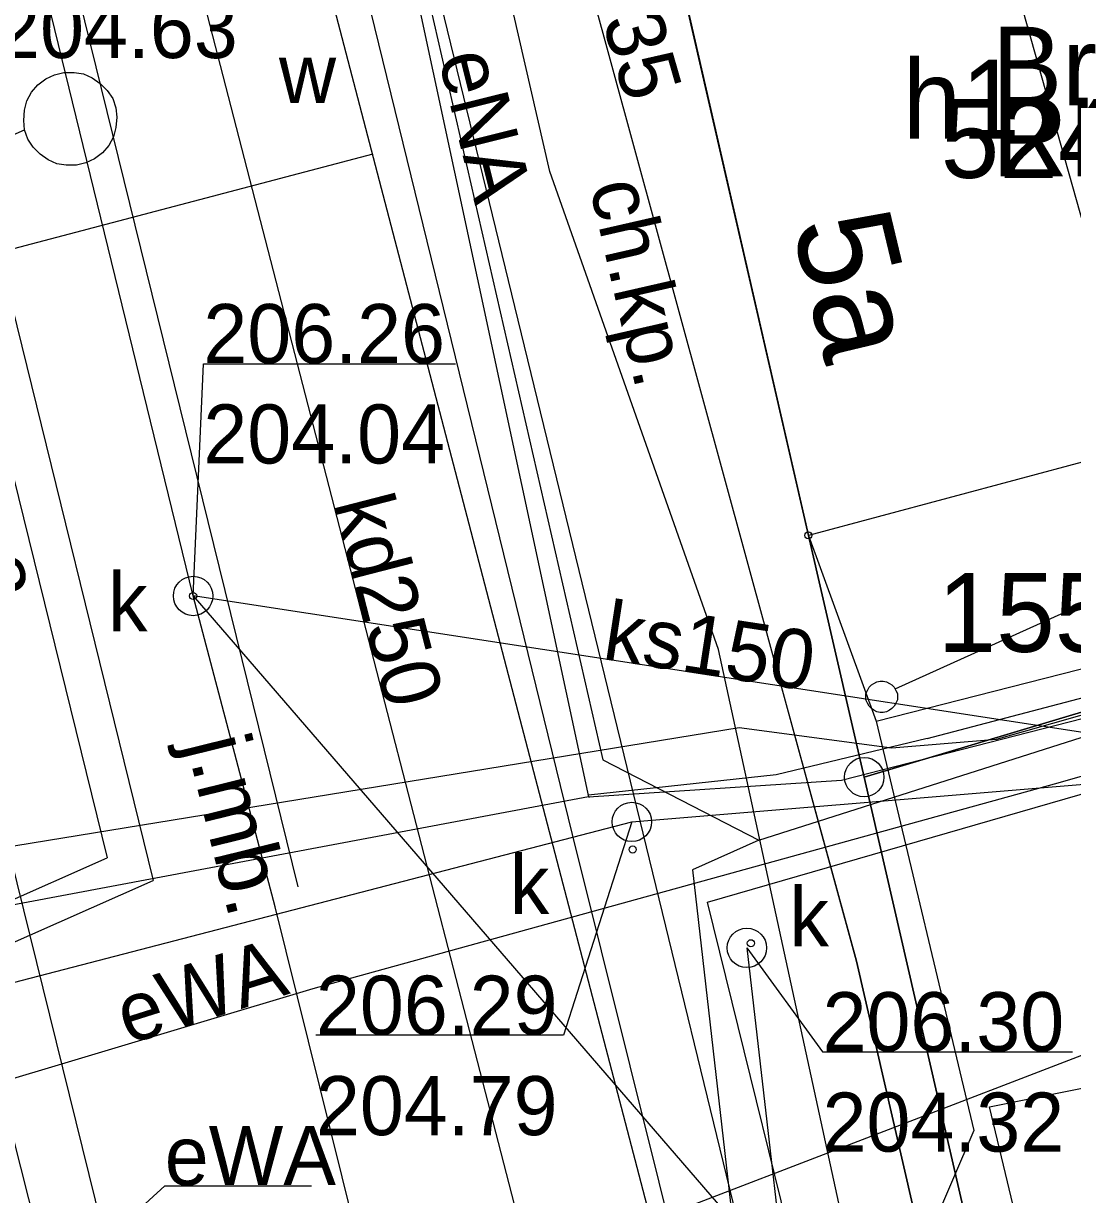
# Model space of a CAD drawing. Extents: x 6512606 to 6513006, y 6022524 to 6022728.
# Drawn here: x 6512859.01 to 6512872.32, y 6022578.56 to 6022593.43 of the extents above; entities that cross this region are included whole.
import ezdxf

# ---------------------------------------------------------------- set-up
doc = ezdxf.new("R2010")
doc.units = 0
for name, color, linetype in [('202-punkt graniczny', 7, 'Continuous'), ('203-punkt graniczny', 7, 'Continuous'), ('209-oznaczenie konturu klasyfikacyjnego', 7, 'Continuous'), ('210-oznaczenie konturu użytku gruntowego', 7, 'Continuous'), ('211-numer działki ewidencyjnej', 7, 'Continuous'), ('217-kontur klasyfikacyjny', 7, 'Continuous'), ('218-kontur użytku gruntowego', 7, 'Continuous'), ('219-działka ewidencyjna', 7, 'Continuous'), ('238-Punkt adresowy budynku', 7, 'Continuous'), ('312-budynek ewidencyjny', 7, 'Continuous'), ('312-oznaczenie budynku ewidencyjnego', 7, 'Continuous'), ('312-oznaczenie budynku ewidencyjnego-Atr117', 7, 'Continuous'), ('4', 7, 'Continuous'), ('996-Tekst dodatkowy mały', 7, 'Continuous'), ('chodnik (powierzchnia)', 7, 'Continuous'), ('chodnik (powierzchnia)-Atr17', 7, 'Continuous'), ('Default', 7, 'Continuous'), ('inna obudowa przewodu - sieć gazowa (linia)', 7, 'Continuous'), ('jezdnia (powierzchnia)', 7, 'Continuous'), ('krawężnik (linia)', 7, 'Continuous'), ('maxp_os', 7, 'Continuous'), ('maxp_ramka_2', 7, 'Continuous'), ('Obszar opracowania', 7, 'Continuous'), ('plac (powierzchnia)', 7, 'Continuous'), ('przewód elektroenergetyczny (linia)', 7, 'Continuous'), ('przewód elektroenergetyczny (linia)-Atr1', 7, 'Continuous'), ('przewód gazowy (linia)', 7, 'Continuous'), ('przewód kanalizacyjny (linia)', 7, 'Continuous'), ('przewód kanalizacyjny (linia)-Atr1', 7, 'Continuous'), ('przewód kanalizacyjny - projektowany lub w budowie (linia) - ob. projektowany', 7, 'Continuous'), ('przewód wodociągowy (linia)', 7, 'Continuous'), ('punkt o określonej wysokości (sieć gazowa)-Atr2', 7, 'Continuous'), ('punkt o określonej wysokości (sieć kanalizacyjna)', 7, 'Continuous'), ('punkt o określonej wysokości (sieć kanalizacyjna)-Atr2', 7, 'Continuous'), ('punkt o określonej wysokości (sieć kanalizacyjna)-Atr3', 7, 'Continuous'), ('punkt o określonej wysokości (sieć wodociągowa)-Atr3', 7, 'Continuous'), ('punkt wysokościowy sztuczny-Atr2', 7, 'Continuous'), ('urządzenie techniczne projektowane lub w budowie (sieć kanalizacyjna) - powierzchnia - ob. projektowany', 7, 'Continuous'), ('właz okrągły - siec kanalizacyjna (punkt)', 7, 'Continuous'), ('właz okrągły - siec kanalizacyjna (punkt)-Atr17', 7, 'Continuous'), ('zasuwa - siec wodociągowa (punkt)-Atr17', 7, 'Continuous')]:
    doc.layers.add(name, color=color, linetype=linetype)

# ---------------------------------------------------------------- blocks, each defined once
blk = doc.blocks.new('202')
at = {"layer": 'Default'}
blk.add_circle((0, 0), 2.5, dxfattribs=at)
blk = doc.blocks.new('203')
at = {"layer": 'Default'}
blk.add_circle((0, 0), 0.45, dxfattribs=at)
blk = doc.blocks.new('US22')
at = {"layer": 'Default'}
blk.add_circle((0, 0), 2.5, dxfattribs=at)
blk = doc.blocks.new('PW01')
at = {"layer": 'Default'}
blk.add_circle((0, 0), 0.45, dxfattribs=at)

msp = doc.modelspace()

# ---------------------------------------------------------------- linework, layer by layer
at = {"layer": '217-kontur klasyfikacyjny'}
for points in [[(6512867.18, 6022594.72), (6512868.97, 6022586.93)], [(6512868.97, 6022586.93), (6512869.68, 6022583.86)], [(6512869.68, 6022583.86), (6512877.43, 6022586.18)], [(6512877.43, 6022586.18), (6512869.68, 6022583.86)], [(6512869.68, 6022583.86), (6512872.457, 6022571.764)]]:
    msp.add_lwpolyline(points, dxfattribs=at)
at = {"layer": '218-kontur użytku gruntowego'}
for points in [[(6512867.18, 6022594.72), (6512868.97, 6022586.93)], [(6512868.97, 6022586.93), (6512867.18, 6022594.72)], [(6512868.97, 6022586.93), (6512869.68, 6022583.86)], [(6512869.68, 6022583.86), (6512868.97, 6022586.93)], [(6512869.68, 6022583.86), (6512877.43, 6022586.18)], [(6512877.43, 6022586.18), (6512869.68, 6022583.86)], [(6512869.68, 6022583.86), (6512872.457, 6022571.764)], [(6512872.457, 6022571.764), (6512869.68, 6022583.86)]]:
    msp.add_lwpolyline(points, dxfattribs=at)
at = {"layer": '219-działka ewidencyjna'}
for points in [[(6512867.18, 6022594.72), (6512868.97, 6022586.93)], [(6512868.97, 6022586.93), (6512869.68, 6022583.86)], [(6512869.68, 6022583.86), (6512877.43, 6022586.18)], [(6512872.457, 6022571.764), (6512869.68, 6022583.86)]]:
    msp.add_lwpolyline(points, dxfattribs=at)
at = {"layer": '312-budynek ewidencyjny'}
for points in [[(6512868.97, 6022586.93), (6512867.18, 6022594.72)], [(6512874.28, 6022588.35), (6512868.97, 6022586.93)], [(6512871.27, 6022579.67), (6512883.235, 6022582.085)], [(6512873.106, 6022572.014), (6512871.27, 6022579.67)]]:
    msp.add_lwpolyline(points, dxfattribs=at)
at = {"layer": '4'}
for points in [[(6512867.18, 6022594.72), (6512868.97, 6022586.93)], [(6512868.97, 6022586.93), (6512869.68, 6022583.86)], [(6512869.68, 6022583.86), (6512877.43, 6022586.18)], [(6512872.457, 6022571.764), (6512869.68, 6022583.86)]]:
    msp.add_lwpolyline(points, dxfattribs=at)
at = {"layer": 'chodnik (powierzchnia)'}
msp.add_lwpolyline([(6512866.67, 6022597.68), (6512867.17, 6022594.8), (6512868.97, 6022586.93)], dxfattribs=at)
at = {"layer": 'inna obudowa przewodu - sieć gazowa (linia)'}
msp.add_lwpolyline([(6512868.52, 6022585.4), (6512869.58, 6022581.52), (6512870.29, 6022578.43), (6512871.862, 6022571.535)], dxfattribs=at)
at = {"layer": 'jezdnia (powierzchnia)'}
msp.add_lwpolyline([(6512858.01, 6022586.22), (6512857.96, 6022585.04), (6512857.46, 6022583.85), (6512856.78, 6022583.14), (6512856.25, 6022582.7), (6512855.73, 6022582.41), (6512857.16, 6022576.8), (6512857.52, 6022576.87), (6512858.5, 6022576.75), (6512859.52, 6022576.13), (6512860.31, 6022575.24), (6512860.92, 6022574.44)], close=True, dxfattribs=at)
at = {"layer": 'krawężnik (linia)'}
msp.add_lwpolyline([(6512862.85, 6022595.89), (6512865.97, 6022583.13), (6512868.17, 6022574.3)], dxfattribs=at)
at = {"layer": 'maxp_os'}
msp.add_line((6512856.906, 6022605.15), (6512862.491, 6022582.465), dxfattribs=at)
at = {"layer": 'maxp_ramka_2'}
for p, q in [((6512854.891, 6022605.956), (6512860.654, 6022582.548)), ((6512854.549, 6022605.257), (6512860.068, 6022582.835)), ((6512856.462, 6022581.237), (6512860.068, 6022582.835)), ((6512856.122, 6022580.54), (6512860.654, 6022582.548))]:
    msp.add_line(p, q, dxfattribs=at)
at = {"layer": 'Obszar opracowania'}
msp.add_lwpolyline([(6512710.98, 6022693.84), (6512748.35, 6022694.16), (6512798.11, 6022695.25), (6512807.47, 6022695.46), (6512809.66, 6022606.87), (6512863.71, 6022622.03), (6512875.13, 6022581.36), (6512755.22, 6022535.25), (6512691.61, 6022568.03), (6512709.16, 6022605.16)], close=True, dxfattribs=at)
at = {"layer": 'plac (powierzchnia)'}
for points in [[(6512868.97, 6022586.93), (6512869.83, 6022584.57), (6512871.07, 6022579.37), (6512870.54, 6022578.14), (6512870.98, 6022575.93), (6512872, 6022576.2), (6512872.2, 6022575.31), (6512871.21, 6022575.06), (6512872.057, 6022571.61)], [(6512869.83, 6022584.57), (6512874.96, 6022585.88)]]:
    msp.add_lwpolyline(points, dxfattribs=at)
at = {"layer": 'przewód elektroenergetyczny (linia)'}
for points in [[(6512802.27, 6022673.66), (6512807.42, 6022670.09), (6512811.38, 6022666.87), (6512814.66, 6022663.43), (6512826.4, 6022651.65), (6512827.82, 6022650.09), (6512834.03, 6022642.46), (6512842.84, 6022631.19), (6512844.67, 6022626.95), (6512847.57, 6022619.87), (6512849.81, 6022612.67), (6512853.56, 6022600.08), (6512856.46, 6022588.83), (6512861.26, 6022569.82), (6512861.768, 6022567.654)], [(6512847.6, 6022616.23), (6512852.12, 6022605.09), (6512853.39, 6022601.13), (6512855.57, 6022592.48), (6512858.1, 6022582.86), (6512868.09, 6022584.49), (6512870.03, 6022584.23), (6512871.36, 6022584.34), (6512875.65, 6022585.56)], [(6512861.56, 6022603.29), (6512861.94, 6022603.39), (6512866.18, 6022583.61), (6512856.81, 6022581.85), (6512858.91, 6022573.95), (6512860.571, 6022567.194)], [(6512861.56, 6022603.29), (6512861.94, 6022603.39), (6512866.36, 6022584.08), (6512868.34, 6022583.06), (6512881.4, 6022587.22)], [(6512869.91, 6022577.24), (6512869.61, 6022577.28), (6512867.83, 6022585.48), (6512865.69, 6022591.55), (6512863.34, 6022601.78), (6512862.79, 6022603.03), (6512861.56, 6022603.29)], [(6512852.76, 6022570.72), (6512852.4, 6022572.17), (6512858.48, 6022574.45), (6512869.09, 6022576.59), (6512867.69, 6022582.27), (6512881.15, 6022586.16), (6512880.7, 6022587.82)], [(6512866.19, 6022583.6), (6512866.18, 6022583.61), (6512869.39, 6022583.82), (6512879.76, 6022586.48), (6512880.2, 6022586.78), (6512880.15, 6022587.67)], [(6512870.48, 6022584.35), (6512881.4, 6022587.22)], [(6512881.03, 6022586.32), (6512872.09, 6022583.77), (6512862.68, 6022581.17), (6512856.97, 6022579.46), (6512860.103, 6022567.013)], [(6512870.48, 6022584.35), (6512868.56, 6022583.89), (6512866.18, 6022583.63)], [(6512866.18, 6022583.61), (6512856.81, 6022581.85), (6512858.91, 6022573.95), (6512860.571, 6022567.194)], [(6512868.34, 6022583.06), (6512867.5, 6022582.68)], [(6512867.5, 6022582.68), (6512868.37, 6022575.03), (6512869.514, 6022570.632)]]:
    msp.add_lwpolyline(points, dxfattribs=at)
at = {"layer": 'przewód elektroenergetyczny (linia)-Atr1'}
msp.add_lwpolyline([(6512857.85, 6022575.97), (6512860.8, 6022578.67), (6512862.661, 6022578.67)], dxfattribs=at)
at = {"layer": 'przewód gazowy (linia)'}
msp.add_lwpolyline([(6512871.862, 6022571.535), (6512870.29, 6022578.43), (6512869.58, 6022581.52), (6512865.64, 6022595.96), (6512860.06, 6022617.51), (6512858.39, 6022625.33), (6512855.49, 6022634.19), (6512854.83, 6022641.62)], dxfattribs=at)
at = {"layer": 'przewód kanalizacyjny (linia)'}
for points in [[(6512861.16, 6022586.16), (6512858.32, 6022597.78), (6512853.7, 6022614.72)], [(6512860.63, 6022596.28), (6512867.451, 6022569.839)], [(6512861.16, 6022586.16), (6512870.65, 6022575.16)], [(6512876.14, 6022584.33), (6512872.95, 6022584.35), (6512861.16, 6022586.16)], [(6512865.461, 6022569.074), (6512862.2, 6022582.21), (6512861.16, 6022586.16)], [(6512866.73, 6022583.29), (6512877.25, 6022584.17), (6512878.82, 6022584.41)], [(6512840.49, 6022576.47), (6512866.73, 6022583.29)], [(6512868.19, 6022581.69), (6512868.88, 6022575.69)]]:
    msp.add_lwpolyline(points, dxfattribs=at)
at = {"layer": 'przewód kanalizacyjny - projektowany lub w budowie (linia) - ob. projektowany'}
for points in [[(6512853.09, 6022589.47), (6512859.02, 6022592.08)], [(6512870.07, 6022584.98), (6512873.76, 6022586.65)]]:
    msp.add_lwpolyline(points, dxfattribs=at)
at = {"layer": 'przewód wodociągowy (linia)'}
for points in [[(6512869.887, 6022570.776), (6512864.23, 6022594.01), (6512863.79, 6022596.02), (6512861.84, 6022602.88)], [(6512869.005, 6022570.437), (6512862.93, 6022593.72)], [(6512863.44, 6022591.77), (6512853.83, 6022589.24)]]:
    msp.add_lwpolyline(points, dxfattribs=at)
at = {"layer": 'punkt o określonej wysokości (sieć kanalizacyjna)-Atr2'}
for points in [[(6512861.16, 6022586.16), (6512861.29, 6022589.11), (6512864.489, 6022589.11)], [(6512866.73, 6022583.29), (6512865.86, 6022580.58), (6512862.719, 6022580.58)], [(6512868.19, 6022581.69), (6512869.15, 6022580.37), (6512872.323, 6022580.37)]]:
    msp.add_lwpolyline(points, dxfattribs=at)
at = {"layer": 'urządzenie techniczne projektowane lub w budowie (sieć kanalizacyjna) - powierzchnia - ob. projektowany'}
for points in [[(6512860.15, 6022591.99), (6512860.09, 6022591.88), (6512860.01, 6022591.79), (6512859.91, 6022591.71), (6512859.8, 6022591.66), (6512859.68, 6022591.63), (6512859.55, 6022591.63), (6512859.43, 6022591.65), (6512859.32, 6022591.7), (6512859.22, 6022591.77), (6512859.13, 6022591.86), (6512859.06, 6022591.96), (6512859.02, 6022592.08), (6512859.01, 6022592.2), (6512859.02, 6022592.33), (6512859.05, 6022592.45), (6512859.11, 6022592.56), (6512859.19, 6022592.65), (6512859.29, 6022592.73), (6512859.4, 6022592.78), (6512859.52, 6022592.81), (6512859.65, 6022592.81), (6512859.77, 6022592.79), (6512859.88, 6022592.74), (6512859.98, 6022592.67), (6512860.07, 6022592.58), (6512860.14, 6022592.48), (6512860.18, 6022592.36), (6512860.19, 6022592.24), (6512860.18, 6022592.11)], [(6512870.1, 6022584.88), (6512870.1, 6022584.84), (6512870.08, 6022584.8), (6512870.06, 6022584.76), (6512870.03, 6022584.73), (6512870, 6022584.71), (6512869.96, 6022584.69), (6512869.92, 6022584.68), (6512869.88, 6022584.68), (6512869.84, 6022584.69), (6512869.8, 6022584.71), (6512869.77, 6022584.73), (6512869.74, 6022584.76), (6512869.72, 6022584.8), (6512869.7, 6022584.84), (6512869.7, 6022584.88), (6512869.7, 6022584.92), (6512869.72, 6022584.96), (6512869.74, 6022585), (6512869.77, 6022585.03), (6512869.8, 6022585.05), (6512869.84, 6022585.07), (6512869.88, 6022585.08), (6512869.92, 6022585.08), (6512869.96, 6022585.07), (6512870, 6022585.05), (6512870.03, 6022585.03), (6512870.06, 6022585), (6512870.08, 6022584.96), (6512870.1, 6022584.92)]]:
    msp.add_lwpolyline(points, close=True, dxfattribs=at)

# ---------------------------------------------------------------- block references
at = {"layer": '202-punkt graniczny', "xscale": 0.1, "yscale": 0.10000000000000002}
msp.add_blockref('202', (6512869.68, 6022583.86), dxfattribs=at)
at = {"layer": '203-punkt graniczny', "xscale": 0.1, "yscale": 0.10000000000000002}
msp.add_blockref('203', (6512868.97, 6022586.93), dxfattribs=at)
at = {"layer": 'punkt o określonej wysokości (sieć kanalizacyjna)', "xscale": 0.1, "yscale": 0.10000000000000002}
for p in [(6512861.16, 6022586.16), (6512866.74, 6022582.94), (6512868.24, 6022581.75)]:
    msp.add_blockref('PW01', p, dxfattribs=at)
at = {"layer": 'właz okrągły - siec kanalizacyjna (punkt)', "xscale": 0.1, "yscale": 0.10000000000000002}
for p in [(6512861.16, 6022586.16), (6512866.73, 6022583.29), (6512868.19, 6022581.69)]:
    msp.add_blockref('US22', p, dxfattribs=at)

# ---------------------------------------------------------------- texts
at = {"layer": '209-oznaczenie konturu klasyfikacyjnego'}
msp.add_text('RIVb', height=1, dxfattribs=at).set_placement((6512871.3, 6022591.49))
at = {"layer": '210-oznaczenie konturu użytku gruntowego'}
msp.add_text('Br', height=1, dxfattribs=at).set_placement((6512871.3, 6022592.39))
at = {"layer": '211-numer działki ewidencyjnej'}
msp.add_text('155', height=1, dxfattribs=at).set_placement((6512870.61, 6022585.45))
at = {"layer": '238-Punkt adresowy budynku'}
msp.add_text('5a', height=1.25, rotation=283.454, dxfattribs=at).set_placement((6512868.76, 6022590.88))
at = {"layer": '312-oznaczenie budynku ewidencyjnego'}
msp.add_text('524', height=1, dxfattribs=at).set_placement((6512870.65, 6022591.47))
at = {"layer": '312-oznaczenie budynku ewidencyjnego-Atr117'}
msp.add_text('h1', height=1, dxfattribs=at).set_placement((6512870.166, 6022591.97))
at = {"layer": '4'}
msp.add_text('155', height=1, dxfattribs=at).set_placement((6512870.61, 6022585.45))
at = {"layer": '996-Tekst dodatkowy mały'}
msp.add_text('j.mb.', height=0.8, rotation=283.875, dxfattribs=at).set_placement((6512861.07, 6022584.29))
at = {"layer": 'chodnik (powierzchnia)-Atr17'}
msp.add_text('ch.kp.', height=0.75, rotation=282.882, dxfattribs=at).set_placement((6512866.19, 6022591.37))
at = {"layer": 'przewód elektroenergetyczny (linia)-Atr1'}
for s, rotation, p in [('eNA', 283.986, (6512864.27, 6022593)), ('eWA', 17.492, (6512860.33, 6022580.46))]:
    msp.add_text(s, height=0.75, rotation=rotation, dxfattribs=at).set_placement(p)
msp.add_text('eWA', height=0.75, dxfattribs=at).set_placement((6512860.8, 6022578.678))
at = {"layer": 'przewód kanalizacyjny (linia)-Atr1'}
for s, rotation, p in [('kd250', 284.465, (6512862.94, 6022587.34)), ('ks150', 351.272, (6512866.34, 6022585.36))]:
    msp.add_text(s, height=0.75, rotation=rotation, dxfattribs=at).set_placement(p)
at = {"layer": 'punkt o określonej wysokości (sieć gazowa)-Atr2'}
msp.add_text('206.35', height=0.75, rotation=286.066, dxfattribs=at).set_placement((6512865.81, 6022595.35))
at = {"layer": 'punkt o określonej wysokości (sieć kanalizacyjna)-Atr2'}
for s, p in [('206.26', (6512861.29, 6022589.118)), ('206.29', (6512862.719, 6022580.588)), ('206.30', (6512869.15, 6022580.378))]:
    msp.add_text(s, height=0.75, dxfattribs=at).set_placement(p)
at = {"layer": 'punkt o określonej wysokości (sieć kanalizacyjna)-Atr3'}
for s, p in [('204.04', (6512861.29, 6022587.843)), ('204.79', (6512862.719, 6022579.312)), ('204.32', (6512869.15, 6022579.103))]:
    msp.add_text(s, height=0.75, dxfattribs=at).set_placement(p)
at = {"layer": 'punkt o określonej wysokości (sieć wodociągowa)-Atr3'}
msp.add_text('204.63', height=0.75, dxfattribs=at).set_placement((6512858.659, 6022592.992))
at = {"layer": 'punkt wysokościowy sztuczny-Atr2'}
msp.add_text('206.08', height=0.75, rotation=286.76, dxfattribs=at).set_placement((6512857.49, 6022588.94))
at = {"layer": 'właz okrągły - siec kanalizacyjna (punkt)-Atr17'}
for p in [(6512860.08, 6022585.71), (6512865.18, 6022582.12), (6512868.73, 6022581.71)]:
    msp.add_text('k', height=0.75, dxfattribs=at).set_placement(p)
at = {"layer": 'zasuwa - siec wodociągowa (punkt)-Atr17'}
msp.add_text('w', height=0.75, dxfattribs=at).set_placement((6512862.25, 6022592.42))

doc.saveas('drawing.dxf')
